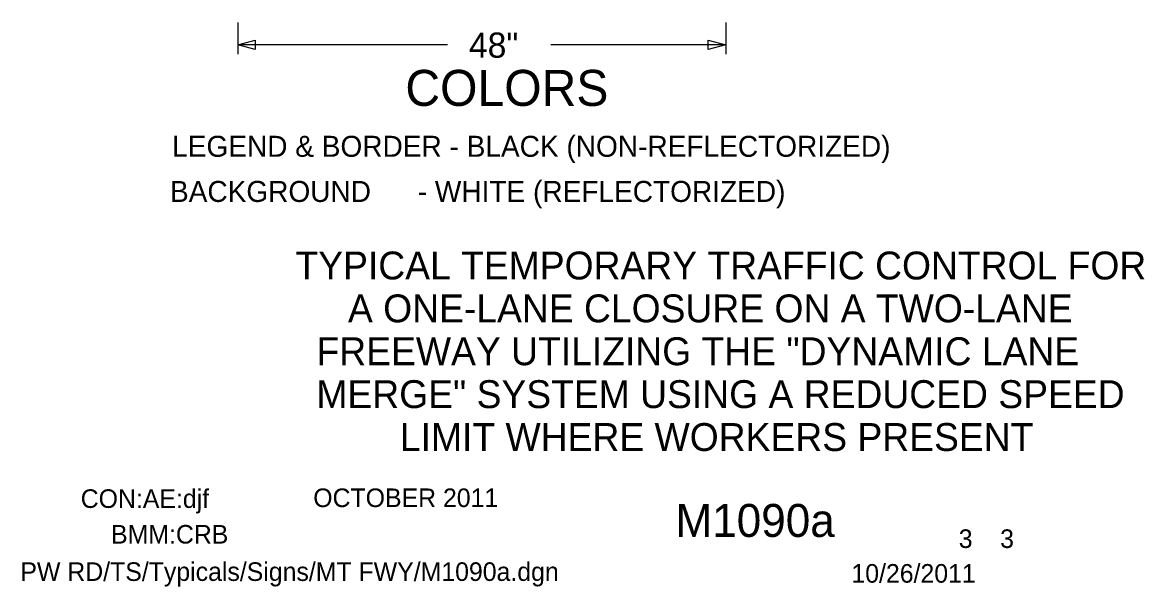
# Model space of a CAD drawing. Extents: x 15278 to 18126, y 1908 to 6555.
# Drawn here: x 17751.9 to 18126.4, y 2176.1 to 2364.2 of the extents above; entities that cross this region are included whole.
import ezdxf

# ---------------------------------------------------------------- set-up
doc = ezdxf.new("R2010")
doc.units = 0
doc.layers.add('BORDER_SIGNAL_WO', color=7, linetype='Continuous')
doc.layers.add('TYPICAL_TEXT_DIMEN_PR', color=7, linetype='Continuous')

msp = doc.modelspace()

# ---------------------------------------------------------------- linework, layer by layer
at = {"layer": 'TYPICAL_TEXT_DIMEN_PR'}
for p, q in [((17823.7, 2364.24), (17823.7, 2353.72)), ((17986.58, 2364.24), (17986.58, 2353.72)), ((17823.7, 2356.82), (17829.57, 2358.39)), ((17893.74, 2356.82), (17823.7, 2356.82)), ((17829.57, 2355.25), (17823.7, 2356.82)), ((17829.57, 2358.39), (17829.57, 2356.82)), ((17829.57, 2356.82), (17829.57, 2355.25)), ((17986.58, 2356.82), (17928.26, 2356.82)), ((17980.71, 2356.82), (17980.71, 2358.39)), ((17980.71, 2358.39), (17986.58, 2356.82)), ((17986.58, 2356.82), (17980.71, 2355.25)), ((17980.71, 2355.25), (17980.71, 2356.82))]:
    msp.add_line(p, q, dxfattribs=at)

# ---------------------------------------------------------------- texts
at = {"layer": 'BORDER_SIGNAL_WO'}
for s, height, p in [('TYPICAL TEMPORARY TRAFFIC CONTROL FOR', 9.3, (17842.98, 2278.54)), ('A ONE-LANE CLOSURE ON A TWO-LANE', 9.3, (17860.5, 2264.24)), ('FREEWAY UTILIZING THE "DYNAMIC LANE', 9.3, (17850, 2249.94)), ('MERGE" SYSTEM USING A REDUCED SPEED', 9.3, (17849.96, 2235.64)), ('LIMIT WHERE WORKERS PRESENT', 9.3, (17877.85, 2221.34)), ('CON:AE:djf  ', 6.2, (17771.3, 2202.35)), ('    OCTOBER 2011    ', 6.2, (17839.7, 2202.63)), ('    M1090a   ', 11, (17953.48, 2192.67)), ('BMM:CRB   ', 6.2, (17781.43, 2190.46)), (' 3    3 ', 6.2, (18062.06, 2188.99)), ('PW RD/TS/Typicals/Signs/MT FWY/M1090a.dgn      ', 6.2, (17751.17, 2178)), ('10/26/2011', 6.2, (18028.54, 2177.42))]:
    msp.add_text(s, height=height, dxfattribs=at).set_placement(p)
at = {"layer": 'TYPICAL_TEXT_DIMEN_PR'}
for s, height, p in [('48"', 8.4, (17900.88, 2352.48)), ('COLORS', 12, (17879.66, 2336.42)), ('LEGEND & BORDER - BLACK (NON-REFLECTORIZED)', 7, (17801.82, 2319.44)), ('BACKGROUND      - WHITE (REFLECTORIZED)', 7, (17801.1, 2304.39))]:
    msp.add_text(s, height=height, dxfattribs=at).set_placement(p)

doc.saveas('drawing.dxf')
